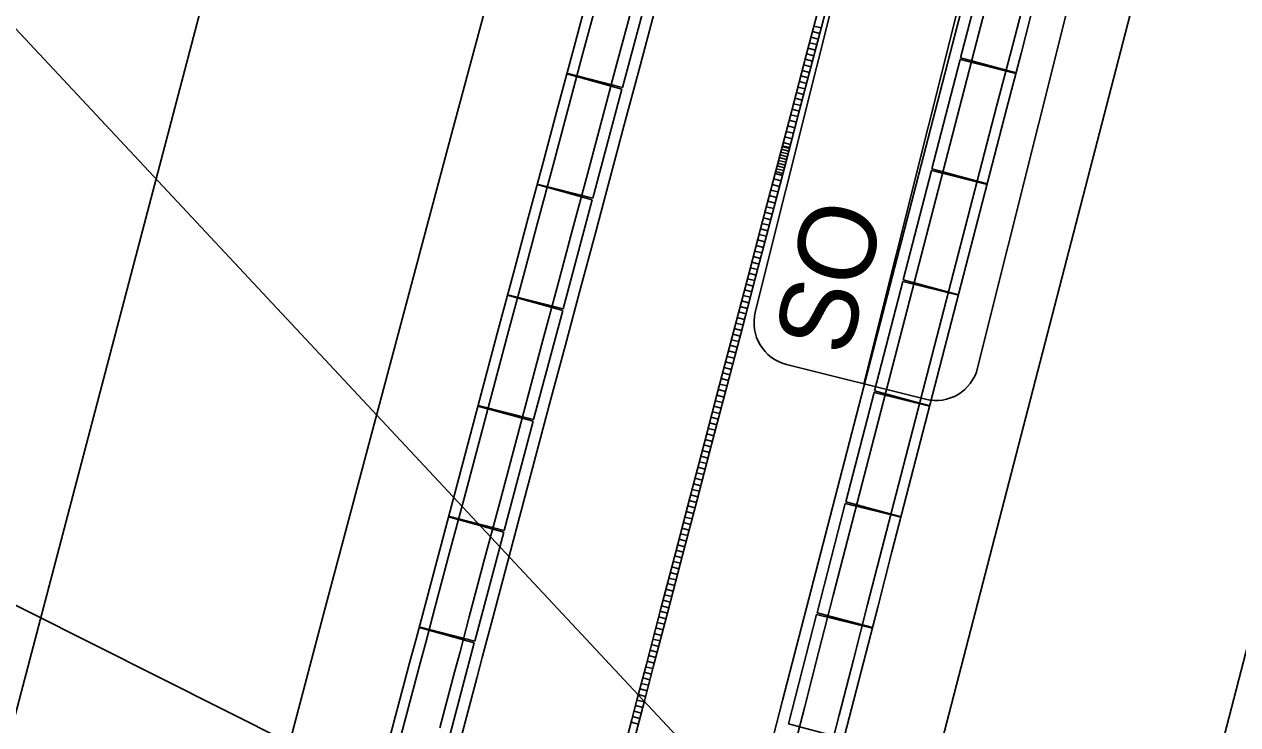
# Model space of a CAD drawing. Extents: x -733601 to -733291, y -1137892 to -1137187.
# Drawn here: x -733436.26 to -733415.08, y -1137606.82 to -1137594.6 of the extents above; entities that cross this region are included whole.
import ezdxf

# ---------------------------------------------------------------- set-up
doc = ezdxf.new("R2010")
doc.units = 0
for name, color, linetype in [('Default', 7, 'Continuous'), ('SIT_PROJ', 7, 'Continuous'), ('SIT_PUV_ZELEZNICE', 7, 'Continuous')]:
    doc.layers.add(name, color=color, linetype=linetype)

# ---------------------------------------------------------------- blocks, each defined once
blk = doc.blocks.new('T_PS_1_4')
at = {"layer": 'Default'}
blk.add_line((-12.486, 3.717), (12.486, 3.717), dxfattribs=at)
for points in [[(10.986, 8), (-10.986, 8)], [(-12.486, 6.5), (-12.486, 1.5)], [(12.486, 1.5), (12.486, 6.5)], [(-10.986, 0), (10.986, 0)]]:
    blk.add_lwpolyline(points, dxfattribs=at)
for centre, start, end in [((-10.986, 6.5), 90, 180), ((10.986, 6.5), 0, 90), ((-10.986, 1.5), 180, 270), ((10.986, 1.5), 270, 360)]:
    blk.add_arc(centre, 1.5, start, end, dxfattribs=at)
blk.add_text('SO', height=2.7, dxfattribs=at).set_placement((-11.75, 4.466))

msp = doc.modelspace()

# ---------------------------------------------------------------- linework, layer by layer
at = {"layer": 'SIT_PROJ'}
for points in [[(-733445.29, -1137585.169), (-733420.477, -1137611.718), (-733420.477, -1137611.718)], [(-733443.08, -1137601.386), (-733424.737, -1137610.597), (-733424.737, -1137610.597)]]:
    msp.add_lwpolyline(points, dxfattribs=at)
at = {"layer": 'SIT_PUV_ZELEZNICE'}
for p, q in [((-733419.419, -1137593.278), (-733419.914, -1137595.185)), ((-733425.306, -1137593.8), (-733425.817, -1137595.702)), ((-733422.374, -1137594.759), (-733422.499, -1137594.726)), ((-733422.348, -1137594.662), (-733422.474, -1137594.629)), ((-733422.45, -1137595.049), (-733422.576, -1137595.016)), ((-733422.425, -1137594.952), (-733422.55, -1137594.919)), ((-733422.399, -1137594.856), (-733422.525, -1137594.822)), ((-733422.501, -1137595.242), (-733422.627, -1137595.209)), ((-733422.476, -1137595.146), (-733422.601, -1137595.112)), ((-733419.921, -1137595.214), (-733420.415, -1137597.121)), ((-733418.951, -1137595.455), (-733419.921, -1137595.214)), ((-733419.914, -1137595.185), (-733418.948, -1137595.446)), ((-733425.817, -1137595.702), (-733426.785, -1137595.453)), ((-733422.552, -1137595.436), (-733422.678, -1137595.402)), ((-733422.527, -1137595.339), (-733422.652, -1137595.306)), ((-733426.788, -1137595.462), (-733425.825, -1137595.731)), ((-733422.603, -1137595.629), (-733422.729, -1137595.596)), ((-733422.578, -1137595.532), (-733422.703, -1137595.499)), ((-733425.825, -1137595.731), (-733426.334, -1137597.634)), ((-733422.654, -1137595.823), (-733422.78, -1137595.789)), ((-733422.629, -1137595.726), (-733422.754, -1137595.693)), ((-733422.731, -1137596.113), (-733422.856, -1137596.079)), ((-733422.705, -1137596.016), (-733422.831, -1137595.983)), ((-733422.68, -1137595.919), (-733422.805, -1137595.886)), ((-733422.781, -1137596.306), (-733422.907, -1137596.273)), ((-733422.756, -1137596.209), (-733422.882, -1137596.176)), ((-733422.832, -1137596.499), (-733422.958, -1137596.466)), ((-733422.807, -1137596.403), (-733422.933, -1137596.369)), ((-733422.898, -1137596.75), (-733423.024, -1137596.717)), ((-733422.883, -1137596.693), (-733423.009, -1137596.66)), ((-733422.858, -1137596.596), (-733422.984, -1137596.563)), ((-733422.953, -1137596.958), (-733423.079, -1137596.925)), ((-733422.94, -1137596.909), (-733423.066, -1137596.876)), ((-733422.928, -1137596.861), (-733423.053, -1137596.828)), ((-733422.915, -1137596.813), (-733423.041, -1137596.779)), ((-733422.902, -1137596.764), (-733423.028, -1137596.731)), ((-733423.004, -1137597.151), (-733423.13, -1137597.118)), ((-733422.991, -1137597.103), (-733423.117, -1137597.07)), ((-733422.979, -1137597.054), (-733423.104, -1137597.021)), ((-733422.966, -1137597.006), (-733423.092, -1137596.973)), ((-733420.415, -1137597.121), (-733419.45, -1137597.382)), ((-733423.051, -1137597.33), (-733423.177, -1137597.297)), ((-733423.026, -1137597.233), (-733423.151, -1137597.2)), ((-733423.026, -1137597.234), (-733423.151, -1137597.2)), ((-733423.017, -1137597.2), (-733423.142, -1137597.166)), ((-733420.423, -1137597.15), (-733420.917, -1137599.057)), ((-733419.452, -1137597.391), (-733420.423, -1137597.15)), ((-733427.305, -1137597.394), (-733426.342, -1137597.662)), ((-733426.334, -1137597.634), (-733427.303, -1137597.385)), ((-733423.102, -1137597.524), (-733423.228, -1137597.491)), ((-733423.077, -1137597.427), (-733423.202, -1137597.394)), ((-733426.342, -1137597.662), (-733426.851, -1137599.565)), ((-733423.178, -1137597.814), (-733423.304, -1137597.781)), ((-733423.153, -1137597.717), (-733423.279, -1137597.684)), ((-733423.128, -1137597.621), (-733423.253, -1137597.587)), ((-733423.229, -1137598.007), (-733423.355, -1137597.974)), ((-733423.204, -1137597.911), (-733423.33, -1137597.877)), ((-733423.28, -1137598.201), (-733423.406, -1137598.168)), ((-733423.255, -1137598.104), (-733423.381, -1137598.071)), ((-733423.331, -1137598.394), (-733423.457, -1137598.361)), ((-733423.306, -1137598.297), (-733423.431, -1137598.264)), ((-733423.382, -1137598.588), (-733423.508, -1137598.554)), ((-733423.357, -1137598.491), (-733423.482, -1137598.458)), ((-733423.433, -1137598.781), (-733423.559, -1137598.748)), ((-733423.407, -1137598.684), (-733423.533, -1137598.651)), ((-733423.509, -1137599.071), (-733423.635, -1137599.038)), ((-733423.484, -1137598.974), (-733423.609, -1137598.941)), ((-733423.458, -1137598.878), (-733423.584, -1137598.845)), ((-733423.56, -1137599.265), (-733423.686, -1137599.231)), ((-733423.535, -1137599.168), (-733423.66, -1137599.135)), ((-733420.925, -1137599.086), (-733421.418, -1137600.993)), ((-733419.954, -1137599.327), (-733420.925, -1137599.086)), ((-733420.917, -1137599.057), (-733419.952, -1137599.318)), ((-733427.822, -1137599.327), (-733426.858, -1137599.594)), ((-733426.851, -1137599.565), (-733427.819, -1137599.317)), ((-733423.611, -1137599.458), (-733423.737, -1137599.425)), ((-733423.586, -1137599.361), (-733423.711, -1137599.328)), ((-733426.858, -1137599.594), (-733427.366, -1137601.497)), ((-733423.662, -1137599.651), (-733423.787, -1137599.618)), ((-733423.636, -1137599.555), (-733423.762, -1137599.522)), ((-733423.713, -1137599.845), (-733423.838, -1137599.812)), ((-733423.687, -1137599.748), (-733423.813, -1137599.715)), ((-733423.789, -1137600.135), (-733423.915, -1137600.102)), ((-733423.763, -1137600.038), (-733423.889, -1137600.005)), ((-733423.738, -1137599.942), (-733423.864, -1137599.908)), ((-733423.84, -1137600.328), (-733423.965, -1137600.295)), ((-733423.814, -1137600.232), (-733423.94, -1137600.199)), ((-733423.891, -1137600.522), (-733424.016, -1137600.489)), ((-733423.865, -1137600.425), (-733423.991, -1137600.392)), ((-733423.941, -1137600.715), (-733424.067, -1137600.682)), ((-733423.916, -1137600.619), (-733424.042, -1137600.585)), ((-733423.992, -1137600.909), (-733424.118, -1137600.876)), ((-733423.967, -1137600.812), (-733424.092, -1137600.779)), ((-733424.068, -1137601.199), (-733424.194, -1137601.166)), ((-733424.043, -1137601.102), (-733424.169, -1137601.069)), ((-733424.018, -1137601.006), (-733424.143, -1137600.972)), ((-733421.426, -1137601.023), (-733421.92, -1137602.93)), ((-733420.455, -1137601.263), (-733421.426, -1137601.023)), ((-733421.418, -1137600.993), (-733420.453, -1137601.254)), ((-733428.338, -1137601.259), (-733427.374, -1137601.526)), ((-733427.366, -1137601.497), (-733428.335, -1137601.249)), ((-733424.119, -1137601.392), (-733424.245, -1137601.359)), ((-733424.094, -1137601.296), (-733424.219, -1137601.262)), ((-733427.374, -1137601.526), (-733427.881, -1137603.43)), ((-733424.17, -1137601.586), (-733424.296, -1137601.553)), ((-733424.145, -1137601.489), (-733424.27, -1137601.456)), ((-733424.221, -1137601.779), (-733424.346, -1137601.746)), ((-733424.195, -1137601.683), (-733424.321, -1137601.649)), ((-733424.272, -1137601.973), (-733424.397, -1137601.939)), ((-733424.246, -1137601.876), (-733424.372, -1137601.843)), ((-733424.348, -1137602.263), (-733424.473, -1137602.23)), ((-733424.322, -1137602.166), (-733424.448, -1137602.133)), ((-733424.297, -1137602.069), (-733424.423, -1137602.036)), ((-733424.398, -1137602.456), (-733424.524, -1137602.423)), ((-733424.373, -1137602.36), (-733424.499, -1137602.326)), ((-733424.449, -1137602.65), (-733424.575, -1137602.617)), ((-733424.424, -1137602.553), (-733424.549, -1137602.52)), ((-733424.5, -1137602.843), (-733424.626, -1137602.81)), ((-733424.475, -1137602.747), (-733424.6, -1137602.713)), ((-733424.551, -1137603.037), (-733424.676, -1137603.003)), ((-733424.525, -1137602.94), (-733424.651, -1137602.907)), ((-733421.927, -1137602.959), (-733422.42, -1137604.866)), ((-733420.956, -1137603.2), (-733421.927, -1137602.959)), ((-733421.92, -1137602.93), (-733420.954, -1137603.19)), ((-733428.852, -1137603.192), (-733427.888, -1137603.458)), ((-733427.881, -1137603.43), (-733428.85, -1137603.182)), ((-733424.601, -1137603.23), (-733424.727, -1137603.197)), ((-733424.576, -1137603.133), (-733424.702, -1137603.1)), ((-733427.888, -1137603.458), (-733428.394, -1137605.362)), ((-733424.678, -1137603.52), (-733424.803, -1137603.487)), ((-733424.652, -1137603.424), (-733424.778, -1137603.39)), ((-733424.627, -1137603.327), (-733424.752, -1137603.294)), ((-733424.728, -1137603.714), (-733424.854, -1137603.681)), ((-733424.703, -1137603.617), (-733424.829, -1137603.584)), ((-733424.779, -1137603.907), (-733424.905, -1137603.874)), ((-733424.754, -1137603.811), (-733424.879, -1137603.777)), ((-733424.83, -1137604.101), (-733424.955, -1137604.067)), ((-733424.804, -1137604.004), (-733424.93, -1137603.971)), ((-733424.88, -1137604.294), (-733425.006, -1137604.261)), ((-733424.855, -1137604.197), (-733424.981, -1137604.164)), ((-733424.956, -1137604.584), (-733425.082, -1137604.551)), ((-733424.931, -1137604.488), (-733425.057, -1137604.454)), ((-733424.906, -1137604.391), (-733425.031, -1137604.358)), ((-733425.007, -1137604.778), (-733425.133, -1137604.745)), ((-733424.982, -1137604.681), (-733425.108, -1137604.648)), ((-733425.058, -1137604.971), (-733425.184, -1137604.938)), ((-733425.033, -1137604.875), (-733425.158, -1137604.841)), ((-733422.428, -1137604.895), (-733422.921, -1137606.802)), ((-733421.457, -1137605.136), (-733422.428, -1137604.895)), ((-733422.42, -1137604.866), (-733421.455, -1137605.126)), ((-733429.366, -1137605.125), (-733428.402, -1137605.391)), ((-733428.394, -1137605.362), (-733429.363, -1137605.115)), ((-733425.109, -1137605.165), (-733425.234, -1137605.132)), ((-733425.083, -1137605.068), (-733425.209, -1137605.035)), ((-733428.402, -1137605.391), (-733428.907, -1137607.295)), ((-733425.159, -1137605.358), (-733425.285, -1137605.325)), ((-733425.134, -1137605.262), (-733425.26, -1137605.228)), ((-733425.235, -1137605.648), (-733425.361, -1137605.615)), ((-733425.21, -1137605.552), (-733425.336, -1137605.519)), ((-733425.185, -1137605.455), (-733425.31, -1137605.422)), ((-733425.286, -1137605.842), (-733425.412, -1137605.809)), ((-733425.261, -1137605.745), (-733425.386, -1137605.712)), ((-733425.337, -1137606.035), (-733425.462, -1137606.002)), ((-733425.311, -1137605.939), (-733425.437, -1137605.905)), ((-733425.387, -1137606.229), (-733425.513, -1137606.196)), ((-733425.362, -1137606.132), (-733425.488, -1137606.099)), ((-733425.438, -1137606.422), (-733425.564, -1137606.389)), ((-733425.413, -1137606.326), (-733425.538, -1137606.292)), ((-733425.489, -1137606.616), (-733425.614, -1137606.583)), ((-733425.463, -1137606.519), (-733425.589, -1137606.486)), ((-733425.539, -1137606.809), (-733425.665, -1137606.776)), ((-733425.514, -1137606.713), (-733425.64, -1137606.679)), ((-733422.921, -1137606.802), (-733421.956, -1137607.063))]:
    msp.add_line(p, q, dxfattribs=at)
for points in [[(-733459.36, -1137757.582), (-733458.338, -1137753.729), (-733455.783, -1137744.061), (-733453.237, -1137734.391), (-733450.698, -1137724.719), (-733448.167, -1137715.044), (-733445.645, -1137705.368), (-733443.13, -1137695.689), (-733440.624, -1137686.008), (-733440.158, -1137684.204), (-733438.123, -1137676.326), (-733435.622, -1137666.644), (-733433.121, -1137656.962), (-733430.62, -1137647.279), (-733428.119, -1137637.597), (-733425.618, -1137627.915), (-733423.422, -1137619.411), (-733423.117, -1137618.233), (-733420.616, -1137608.551), (-733418.11, -1137598.87), (-733415.599, -1137589.19), (-733413.078, -1137579.513), (-733412.782, -1137578.384)], [(-733453.981, -1137756.29), (-733452.315, -1137749.966), (-733449.778, -1137740.293), (-733447.253, -1137730.617), (-733444.741, -1137720.938), (-733443.633, -1137716.651), (-733442.239, -1137711.256), (-733439.738, -1137701.574), (-733437.237, -1137691.892), (-733434.736, -1137682.209), (-733432.235, -1137672.527), (-733429.735, -1137662.844), (-733427.234, -1137653.162), (-733424.733, -1137643.48), (-733422.232, -1137633.798), (-733419.731, -1137624.116), (-733417.23, -1137614.434), (-733415.895, -1137609.267), (-733414.728, -1137604.752), (-733412.218, -1137595.072), (-733409.698, -1137585.394), (-733408.191, -1137579.632)], [(-733469.582, -1137755.14), (-733468.663, -1137751.534), (-733466.195, -1137741.843), (-733463.726, -1137732.153), (-733461.257, -1137722.462), (-733458.789, -1137712.772), (-733456.32, -1137703.081), (-733453.852, -1137693.391), (-733451.383, -1137683.701), (-733451.044, -1137682.371), (-733448.914, -1137674.01), (-733446.443, -1137664.32), (-733443.966, -1137654.632), (-733441.48, -1137644.946), (-733438.982, -1137635.263), (-733436.47, -1137625.584), (-733433.94, -1137615.909), (-733431.39, -1137606.239), (-733431.038, -1137604.913), (-733428.815, -1137596.577), (-733426.217, -1137586.92), (-733424.808, -1137581.736)], [(-733473.591, -1137751.638), (-733472.603, -1137747.76), (-733470.135, -1137738.069), (-733467.666, -1137728.379), (-733465.198, -1137718.688), (-733462.729, -1137708.998), (-733460.26, -1137699.307), (-733457.792, -1137689.617), (-733455.323, -1137679.926), (-733452.855, -1137670.236), (-733450.386, -1137660.545), (-733448.734, -1137654.061), (-733447.917, -1137650.855), (-733445.432, -1137641.168), (-733442.928, -1137631.487), (-733440.405, -1137621.811), (-733437.862, -1137612.139), (-733437.8, -1137611.906), (-733435.314, -1137602.469), (-733432.775, -1137592.797), (-733432.613, -1137592.177)], [(-733423.181, -1137607.007), (-733423.024, -1137606.4), (-733422.774, -1137605.434), (-733422.524, -1137604.468), (-733422.274, -1137603.502), (-733422.024, -1137602.536), (-733421.774, -1137601.57), (-733421.524, -1137600.604), (-733421.274, -1137599.638), (-733421.024, -1137598.672), (-733420.774, -1137597.706), (-733420.524, -1137596.741), (-733420.273, -1137595.775), (-733420.023, -1137594.809), (-733419.772, -1137593.843)], [(-733422.793, -1137607.107), (-733422.636, -1137606.5), (-733422.387, -1137605.534), (-733422.137, -1137604.568), (-733421.887, -1137603.602), (-733421.637, -1137602.636), (-733421.387, -1137601.67), (-733421.137, -1137600.704), (-733420.887, -1137599.739), (-733420.637, -1137598.773), (-733420.387, -1137597.807), (-733420.136, -1137596.841), (-733419.886, -1137595.875), (-733419.636, -1137594.909), (-733419.385, -1137593.943)], [(-733430.031, -1137607.633), (-733429.775, -1137606.667), (-733429.519, -1137605.701), (-733429.424, -1137605.342), (-733429.262, -1137604.735), (-733429.006, -1137603.769), (-733428.749, -1137602.803), (-733428.492, -1137601.837), (-733428.234, -1137600.871), (-733427.977, -1137599.905), (-733427.719, -1137598.939), (-733427.46, -1137597.974), (-733427.202, -1137597.008), (-733426.943, -1137596.043), (-733426.685, -1137595.077), (-733426.425, -1137594.112)], [(-733429.857, -1137607.68), (-733429.601, -1137606.713), (-733429.345, -1137605.747), (-733429.25, -1137605.388), (-733429.088, -1137604.781), (-733428.832, -1137603.815), (-733428.575, -1137602.849), (-733428.318, -1137601.883), (-733428.06, -1137600.917), (-733427.803, -1137599.952), (-733427.545, -1137598.986), (-733427.287, -1137598.02), (-733427.028, -1137597.055), (-733426.77, -1137596.089), (-733426.511, -1137595.124), (-733426.252, -1137594.158)], [(-733425.905, -1137607.693), (-733425.652, -1137606.727), (-733425.558, -1137606.368), (-733425.399, -1137605.761), (-733425.146, -1137604.795), (-733424.893, -1137603.829), (-733424.64, -1137602.863), (-733424.386, -1137601.897), (-733424.133, -1137600.932), (-733423.879, -1137599.966), (-733423.625, -1137599), (-733423.371, -1137598.034), (-733423.117, -1137597.069), (-733422.862, -1137596.103), (-733422.608, -1137595.137), (-733422.353, -1137594.172)], [(-733422.353, -1137594.172), (-733422.608, -1137595.137), (-733422.862, -1137596.103), (-733423.024, -1137596.717), (-733422.898, -1137596.75), (-733422.737, -1137596.136), (-733422.482, -1137595.17), (-733422.228, -1137594.205)], [(-733422.193, -1137607.262), (-733422.036, -1137606.655), (-733421.786, -1137605.689), (-733421.537, -1137604.723), (-733421.287, -1137603.757), (-733421.037, -1137602.792), (-733420.787, -1137601.826), (-733420.537, -1137600.86), (-733420.287, -1137599.894), (-733420.037, -1137598.928), (-733419.786, -1137597.962), (-733419.536, -1137596.996), (-733419.286, -1137596.031), (-733419.035, -1137595.065), (-733418.785, -1137594.099)], [(-733422.019, -1137607.307), (-733421.862, -1137606.7), (-733421.612, -1137605.734), (-733421.362, -1137604.768), (-733421.113, -1137603.803), (-733420.863, -1137602.837), (-733420.613, -1137601.871), (-733420.363, -1137600.905), (-733420.113, -1137599.939), (-733419.862, -1137598.973), (-733419.612, -1137598.007), (-733419.362, -1137597.042), (-733419.112, -1137596.076), (-733418.861, -1137595.11), (-733418.611, -1137594.144)], [(-733429.002, -1137606.872), (-733428.746, -1137605.906), (-733428.65, -1137605.547), (-733428.489, -1137604.94), (-733428.233, -1137603.974), (-733427.976, -1137603.009), (-733427.719, -1137602.043), (-733427.461, -1137601.077), (-733427.204, -1137600.112), (-733426.946, -1137599.146), (-733426.688, -1137598.18), (-733426.429, -1137597.215), (-733426.171, -1137596.25), (-733425.912, -1137595.284), (-733425.653, -1137594.319)], [(-733425.779, -1137607.726), (-733425.526, -1137606.76), (-733425.432, -1137606.401), (-733425.273, -1137605.794), (-733425.02, -1137604.828), (-733424.767, -1137603.862), (-733424.514, -1137602.896), (-733424.26, -1137601.93), (-733424.007, -1137600.965), (-733423.753, -1137599.999), (-733423.499, -1137599.033), (-733423.245, -1137598.067), (-733422.991, -1137597.102), (-733422.737, -1137596.136), (-733422.482, -1137595.17), (-733422.228, -1137594.205)], [(-733428.615, -1137606.975), (-733428.359, -1137606.009), (-733428.264, -1137605.65), (-733428.103, -1137605.043), (-733427.846, -1137604.077), (-733427.589, -1137603.111), (-733427.332, -1137602.146), (-733427.075, -1137601.18), (-733426.817, -1137600.215), (-733426.559, -1137599.249), (-733426.301, -1137598.284), (-733426.043, -1137597.319), (-733425.784, -1137596.353), (-733425.526, -1137595.388), (-733425.267, -1137594.423)], [(-733425.779, -1137607.726), (-733425.526, -1137606.76), (-733425.432, -1137606.401), (-733425.273, -1137605.794), (-733425.02, -1137604.828), (-733424.767, -1137603.862), (-733424.514, -1137602.896), (-733424.26, -1137601.93), (-733424.007, -1137600.965), (-733423.753, -1137599.999), (-733423.499, -1137599.033), (-733423.245, -1137598.067), (-733423.026, -1137597.233), (-733423.151, -1137597.2), (-733423.371, -1137598.034), (-733423.625, -1137599), (-733423.879, -1137599.966), (-733424.133, -1137600.932), (-733424.386, -1137601.897), (-733424.64, -1137602.863), (-733424.893, -1137603.829), (-733425.146, -1137604.795), (-733425.399, -1137605.761), (-733425.558, -1137606.368), (-733425.652, -1137606.727), (-733425.905, -1137607.693)]]:
    msp.add_lwpolyline(points, dxfattribs=at)
msp.add_lwpolyline([(-733422.898, -1137596.75), (-733423.024, -1137596.717), (-733423.117, -1137597.069), (-733423.151, -1137597.2), (-733423.026, -1137597.233), (-733422.991, -1137597.102), (-733422.966, -1137597.005)], close=True, dxfattribs=at)

# ---------------------------------------------------------------- block references
at = {"layer": 'SIT_PROJ', "xscale": 0.4999999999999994, "yscale": 0.49999999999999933, "rotation": 75.93557209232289}
msp.add_blockref('T_PS_1_4', (-733418.283, -1137595.267), dxfattribs=at)

doc.saveas('drawing.dxf')
